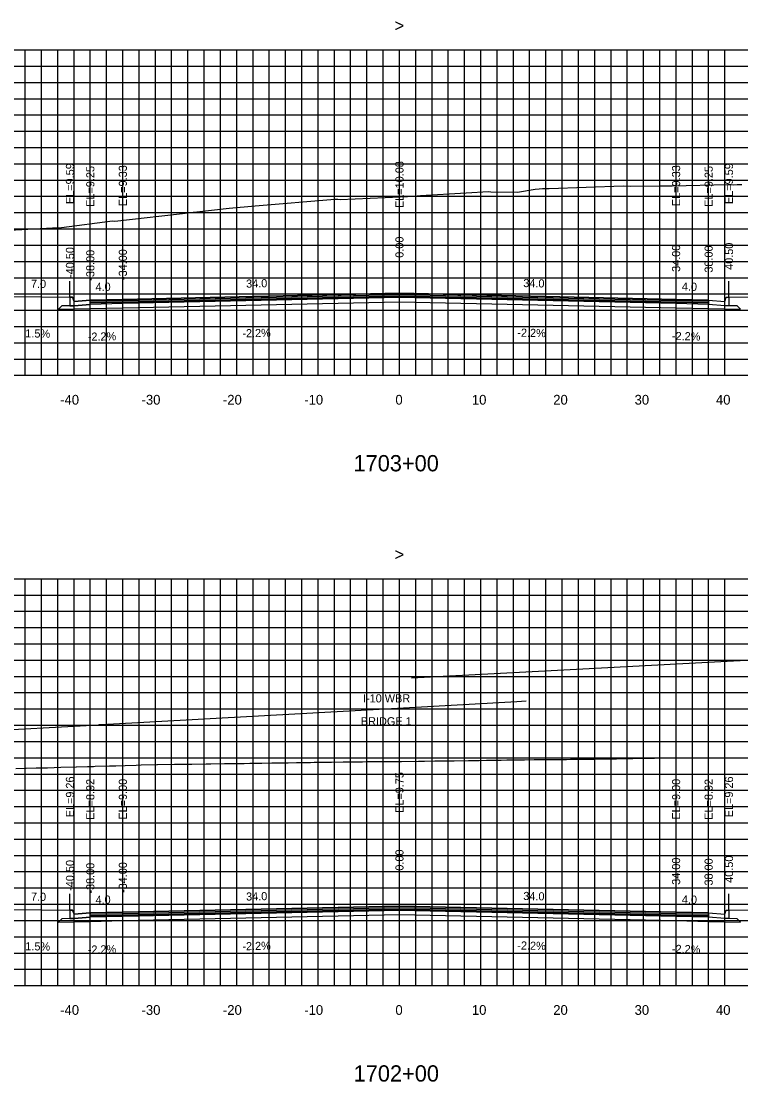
# Model space of a CAD drawing. Extents: x 1797789 to 1803805, y 249066 to 250293.
# Drawn here: x 1802584.5 to 1802673, y 250087.6 to 250218 of the extents above; entities that cross this region are included whole.
import ezdxf

# ---------------------------------------------------------------- set-up
doc = ezdxf.new("R2010")
doc.units = 0
for name, color, linetype in [('1', 7, 'Continuous'), ('10', 7, 'Continuous'), ('3', 7, 'Continuous'), ('4', 7, 'Continuous'), ('60', 7, 'Continuous'), ('BASE', 7, 'Continuous'), ('CL-CNST', 7, 'Continuous'), ('Level 62', 7, 'Continuous'), ('LOWER BINDER', 7, 'Continuous'), ('M-ROADS', 7, 'Continuous'), ('UPPER BINDER', 7, 'Continuous'), ('WEARING', 7, 'Continuous')]:
    doc.layers.add(name, color=color, linetype=linetype)

msp = doc.modelspace()

# ---------------------------------------------------------------- linework, layer by layer
for p, q in [((1802631, 250184.51), (1802631, 250186.51)), ((1802590.5, 250184.02), (1802590.5, 250186.02)), ((1802590.5, 250184.02), (1802590.5, 250186.02)), ((1802593, 250183.68), (1802593, 250185.68)), ((1802597, 250183.77), (1802597, 250185.77)), ((1802665, 250183.77), (1802665, 250185.77)), ((1802669, 250183.68), (1802669, 250185.68)), ((1802671.5, 250184.02), (1802671.5, 250186.02)), ((1802671.5, 250184.02), (1802671.5, 250186.02)), ((1802631, 250109.18), (1802631, 250111.18)), ((1802590.5, 250108.69), (1802590.5, 250110.69)), ((1802590.5, 250108.69), (1802590.5, 250110.69)), ((1802593, 250108.35), (1802593, 250110.35)), ((1802597, 250108.44), (1802597, 250110.44)), ((1802665, 250108.44), (1802665, 250110.44)), ((1802669, 250108.35), (1802669, 250110.35)), ((1802671.5, 250108.69), (1802671.5, 250110.69)), ((1802671.5, 250108.69), (1802671.5, 250110.69))]:
    msp.add_line(p, q)
for points in [[(1802593, 250183.68), (1802591, 250183.52), (1802590.83, 250184.02), (1802590.5, 250184.02), (1802590.5, 250182.99), (1802591, 250182.99), (1802593, 250183.15)], [(1802669, 250183.68), (1802671, 250183.52), (1802671.17, 250184.02), (1802671.5, 250184.02), (1802671.5, 250182.99), (1802671, 250182.99), (1802669, 250183.15)], [(1802593, 250108.35), (1802591, 250108.19), (1802590.83, 250108.69), (1802590.5, 250108.69), (1802590.5, 250107.66), (1802591, 250107.66), (1802593, 250107.82)], [(1802669, 250108.35), (1802671, 250108.19), (1802671.17, 250108.69), (1802671.5, 250108.69), (1802671.5, 250107.66), (1802671, 250107.66), (1802669, 250107.82)]]:
    msp.add_lwpolyline(points, close=True)
at = {"layer": '60'}
for p, q in [((1802481, 250174.43), (1802781, 250174.43)), ((1802591, 250174.37), (1802591, 250174.43)), ((1802601, 250174.37), (1802601, 250174.43)), ((1802611, 250174.37), (1802611, 250174.43)), ((1802621, 250174.37), (1802621, 250174.43)), ((1802631, 250174.37), (1802631, 250174.43)), ((1802641, 250174.37), (1802641, 250174.43)), ((1802651, 250174.37), (1802651, 250174.43)), ((1802661, 250174.37), (1802661, 250174.43)), ((1802671, 250174.37), (1802671, 250174.43)), ((1802481, 250099.43), (1802781, 250099.43)), ((1802591, 250099.37), (1802591, 250099.43)), ((1802601, 250099.37), (1802601, 250099.43)), ((1802611, 250099.37), (1802611, 250099.43)), ((1802621, 250099.37), (1802621, 250099.43)), ((1802631, 250099.37), (1802631, 250099.43)), ((1802641, 250099.37), (1802641, 250099.43)), ((1802651, 250099.37), (1802651, 250099.43)), ((1802661, 250099.37), (1802661, 250099.43)), ((1802671, 250099.37), (1802671, 250099.43))]:
    msp.add_line(p, q, dxfattribs=at)
at = {"layer": 'BASE'}
for points in [[(1802669, 250182.65), (1802672.9, 250182.56), (1802672.5, 250182.97), (1802671.5, 250182.99), (1802671, 250182.99), (1802669, 250183.15), (1802665, 250183.24), (1802631, 250183.98), (1802597, 250183.24), (1802593, 250183.15), (1802591, 250182.99), (1802590.5, 250182.99), (1802589.5, 250182.97), (1802589.1, 250182.56), (1802593, 250182.65), (1802597, 250182.74), (1802631, 250183.48), (1802665, 250182.74)], [(1802669, 250107.32), (1802672.9, 250107.23), (1802672.5, 250107.64), (1802671.5, 250107.66), (1802671, 250107.66), (1802669, 250107.82), (1802665, 250107.91), (1802631, 250108.65), (1802597, 250107.91), (1802593, 250107.82), (1802591, 250107.66), (1802590.5, 250107.66), (1802589.5, 250107.64), (1802589.1, 250107.23), (1802593, 250107.32), (1802597, 250107.41), (1802631, 250108.15), (1802665, 250107.41)]]:
    msp.add_lwpolyline(points, close=True, dxfattribs=at)
at = {"layer": 'CL-CNST'}
for points in [[(1802481, 250187.57), (1802582.5, 250184.16), (1802583.5, 250184.12), (1802590.5, 250184.02), (1802590.5, 250184.02), (1802590.83, 250184.02), (1802591, 250183.52), (1802593, 250183.68), (1802597, 250183.77), (1802631, 250184.51), (1802665, 250183.77), (1802669, 250183.68), (1802671, 250183.52), (1802671.17, 250184.02), (1802671.5, 250184.02), (1802671.5, 250184.02), (1802678.5, 250184.12), (1802679.5, 250184.16), (1802781, 250184.59)], [(1802632.47, 250137.25), (1802644.2, 250137.87), (1802653.52, 250138.36), (1802665.04, 250138.96), (1802679.9, 250139.73), (1802688.39, 250140.16), (1802691.29, 250140.31), (1802692.92, 250140.4), (1802696.16, 250140.56), (1802706.65, 250141.08), (1802715.8, 250141.54), (1802725.76, 250141.98), (1802729.55, 250142.04), (1802733.81, 250142.1), (1802742.28, 250142.22), (1802749.58, 250142.28), (1802750.71, 250142.3), (1802752.52, 250142.31)], [(1802481, 250125.67), (1802485.7, 250125.45), (1802489.05, 250125.3), (1802499.2, 250124.76), (1802500.03, 250124.72), (1802503.77, 250124.83), (1802509.21, 250124.99), (1802512.64, 250125.27), (1802514, 250125.39), (1802517.65, 250125.7), (1802540.82, 250127.67), (1802567.56, 250130.03), (1802570.52, 250130.2), (1802572.85, 250130.32), (1802578.86, 250130.66), (1802593.99, 250131.49), (1802594.15, 250131.5), (1802594.36, 250131.51), (1802632.25, 250133.61), (1802645.42, 250134.34), (1802646.58, 250134.41)], [(1802529.01, 250126.66), (1802582.5, 250108.83), (1802583.5, 250108.79), (1802590.5, 250108.69), (1802590.5, 250108.69), (1802590.83, 250108.69), (1802591, 250108.19), (1802593, 250108.35), (1802597, 250108.44), (1802631, 250109.18), (1802665, 250108.44), (1802669, 250108.35), (1802671, 250108.19), (1802671.17, 250108.69), (1802671.5, 250108.69), (1802671.5, 250108.69), (1802678.5, 250108.79), (1802679.5, 250108.83), (1802781, 250109.41)]]:
    msp.add_lwpolyline(points, dxfattribs=at)
at = {"layer": 'Level 62'}
for p, q in [((1802481, 250214.43), (1802781, 250214.43)), ((1802585, 250174.43), (1802585, 250214.43)), ((1802587, 250174.43), (1802587, 250214.43)), ((1802589, 250174.43), (1802589, 250214.43)), ((1802591, 250174.43), (1802591, 250214.43)), ((1802593, 250174.43), (1802593, 250214.43)), ((1802595, 250174.43), (1802595, 250214.43)), ((1802597, 250174.43), (1802597, 250214.43)), ((1802599, 250174.43), (1802599, 250214.43)), ((1802601, 250174.43), (1802601, 250214.43)), ((1802603, 250174.43), (1802603, 250214.43)), ((1802605, 250174.43), (1802605, 250214.43)), ((1802607, 250174.43), (1802607, 250214.43)), ((1802609, 250174.43), (1802609, 250214.43)), ((1802611, 250174.43), (1802611, 250214.43)), ((1802613, 250174.43), (1802613, 250214.43)), ((1802615, 250174.43), (1802615, 250214.43)), ((1802617, 250174.43), (1802617, 250214.43)), ((1802619, 250174.43), (1802619, 250214.43)), ((1802621, 250174.43), (1802621, 250214.43)), ((1802623, 250174.43), (1802623, 250214.43)), ((1802625, 250174.43), (1802625, 250214.43)), ((1802627, 250174.43), (1802627, 250214.43)), ((1802629, 250174.43), (1802629, 250214.43)), ((1802631, 250174.43), (1802631, 250214.43)), ((1802633, 250174.43), (1802633, 250214.43)), ((1802635, 250174.43), (1802635, 250214.43)), ((1802637, 250174.43), (1802637, 250214.43)), ((1802639, 250174.43), (1802639, 250214.43)), ((1802641, 250174.43), (1802641, 250214.43)), ((1802643, 250174.43), (1802643, 250214.43)), ((1802645, 250174.43), (1802645, 250214.43)), ((1802647, 250174.43), (1802647, 250214.43)), ((1802649, 250174.43), (1802649, 250214.43)), ((1802651, 250174.43), (1802651, 250214.43)), ((1802653, 250174.43), (1802653, 250214.43)), ((1802655, 250174.43), (1802655, 250214.43)), ((1802657, 250174.43), (1802657, 250214.43)), ((1802659, 250174.43), (1802659, 250214.43)), ((1802661, 250174.43), (1802661, 250214.43)), ((1802663, 250174.43), (1802663, 250214.43)), ((1802665, 250174.43), (1802665, 250214.43)), ((1802667, 250174.43), (1802667, 250214.43)), ((1802669, 250174.43), (1802669, 250214.43)), ((1802671, 250174.43), (1802671, 250214.43)), ((1802481, 250212.43), (1802781, 250212.43)), ((1802481, 250210.43), (1802781, 250210.43)), ((1802481, 250208.43), (1802781, 250208.43)), ((1802481, 250206.43), (1802781, 250206.43)), ((1802481, 250204.43), (1802781, 250204.43)), ((1802481, 250202.43), (1802781, 250202.43)), ((1802481, 250200.43), (1802781, 250200.43)), ((1802481, 250198.43), (1802781, 250198.43)), ((1802481, 250196.43), (1802781, 250196.43)), ((1802481, 250194.43), (1802781, 250194.43)), ((1802481, 250192.43), (1802781, 250192.43)), ((1802481, 250190.43), (1802781, 250190.43)), ((1802481, 250188.43), (1802781, 250188.43)), ((1802481, 250186.43), (1802781, 250186.43)), ((1802481, 250184.43), (1802781, 250184.43)), ((1802481, 250182.43), (1802781, 250182.43)), ((1802481, 250180.43), (1802781, 250180.43)), ((1802481, 250178.43), (1802781, 250178.43)), ((1802481, 250176.43), (1802781, 250176.43)), ((1802481, 250174.43), (1802781, 250174.43)), ((1802481, 250149.43), (1802781, 250149.43)), ((1802585, 250099.43), (1802585, 250149.43)), ((1802587, 250099.43), (1802587, 250149.43)), ((1802589, 250099.43), (1802589, 250149.43)), ((1802591, 250099.43), (1802591, 250149.43)), ((1802593, 250099.43), (1802593, 250149.43)), ((1802595, 250099.43), (1802595, 250149.43)), ((1802597, 250099.43), (1802597, 250149.43)), ((1802599, 250099.43), (1802599, 250149.43)), ((1802601, 250099.43), (1802601, 250149.43)), ((1802603, 250099.43), (1802603, 250149.43)), ((1802605, 250099.43), (1802605, 250149.43)), ((1802607, 250099.43), (1802607, 250149.43)), ((1802609, 250099.43), (1802609, 250149.43)), ((1802611, 250099.43), (1802611, 250149.43)), ((1802613, 250099.43), (1802613, 250149.43)), ((1802615, 250099.43), (1802615, 250149.43)), ((1802617, 250099.43), (1802617, 250149.43)), ((1802619, 250099.43), (1802619, 250149.43)), ((1802621, 250099.43), (1802621, 250149.43)), ((1802623, 250099.43), (1802623, 250149.43)), ((1802625, 250099.43), (1802625, 250149.43)), ((1802627, 250099.43), (1802627, 250149.43)), ((1802629, 250099.43), (1802629, 250149.43)), ((1802631, 250099.43), (1802631, 250149.43)), ((1802633, 250099.43), (1802633, 250149.43)), ((1802635, 250099.43), (1802635, 250149.43)), ((1802637, 250099.43), (1802637, 250149.43)), ((1802639, 250099.43), (1802639, 250149.43)), ((1802641, 250099.43), (1802641, 250149.43)), ((1802643, 250099.43), (1802643, 250149.43)), ((1802645, 250099.43), (1802645, 250149.43)), ((1802647, 250099.43), (1802647, 250149.43)), ((1802649, 250099.43), (1802649, 250149.43)), ((1802651, 250099.43), (1802651, 250149.43)), ((1802653, 250099.43), (1802653, 250149.43)), ((1802655, 250099.43), (1802655, 250149.43)), ((1802657, 250099.43), (1802657, 250149.43)), ((1802659, 250099.43), (1802659, 250149.43)), ((1802661, 250099.43), (1802661, 250149.43)), ((1802663, 250099.43), (1802663, 250149.43)), ((1802665, 250099.43), (1802665, 250149.43)), ((1802667, 250099.43), (1802667, 250149.43)), ((1802669, 250099.43), (1802669, 250149.43)), ((1802671, 250099.43), (1802671, 250149.43)), ((1802481, 250147.43), (1802781, 250147.43)), ((1802481, 250145.43), (1802781, 250145.43)), ((1802481, 250143.43), (1802781, 250143.43)), ((1802481, 250141.43), (1802781, 250141.43)), ((1802481, 250139.43), (1802781, 250139.43)), ((1802481, 250137.43), (1802781, 250137.43)), ((1802481, 250135.43), (1802781, 250135.43)), ((1802481, 250133.43), (1802781, 250133.43)), ((1802481, 250131.43), (1802781, 250131.43)), ((1802481, 250129.43), (1802781, 250129.43)), ((1802481, 250127.43), (1802781, 250127.43)), ((1802481, 250125.43), (1802781, 250125.43)), ((1802481, 250123.43), (1802781, 250123.43)), ((1802481, 250121.43), (1802781, 250121.43)), ((1802481, 250119.43), (1802781, 250119.43)), ((1802481, 250117.43), (1802781, 250117.43)), ((1802481, 250115.43), (1802781, 250115.43)), ((1802481, 250113.43), (1802781, 250113.43)), ((1802481, 250111.43), (1802781, 250111.43)), ((1802481, 250109.43), (1802781, 250109.43)), ((1802481, 250107.43), (1802781, 250107.43)), ((1802481, 250105.43), (1802781, 250105.43)), ((1802481, 250103.43), (1802781, 250103.43)), ((1802481, 250101.43), (1802781, 250101.43)), ((1802481, 250099.43), (1802781, 250099.43))]:
    msp.add_line(p, q, dxfattribs=at)
at = {"layer": 'LOWER BINDER'}
for points in [[(1802593, 250183.15), (1802593, 250183.34), (1802597, 250183.43), (1802631, 250184.17), (1802665, 250183.43), (1802669, 250183.34), (1802669, 250183.15), (1802665, 250183.24), (1802631, 250183.98), (1802597, 250183.24)], [(1802593, 250107.82), (1802593, 250108.01), (1802597, 250108.1), (1802631, 250108.84), (1802665, 250108.1), (1802669, 250108.01), (1802669, 250107.82), (1802665, 250107.91), (1802631, 250108.65), (1802597, 250107.91)]]:
    msp.add_lwpolyline(points, close=True, dxfattribs=at)
at = {"layer": 'M-ROADS'}
for points in [[(1802573.92, 250191.76), (1802588.37, 250192.57), (1802588.4, 250192.56), (1802588.89, 250192.55), (1802589.05, 250192.55), (1802589.27, 250192.55), (1802589.48, 250192.58), (1802595.71, 250193.42), (1802596, 250193.39), (1802605.4, 250194.44), (1802605.64, 250194.47), (1802606.09, 250194.52), (1802610.07, 250194.98), (1802613.26, 250195.27), (1802623.07, 250196.07), (1802623.29, 250196.1), (1802623.42, 250196.08), (1802623.7, 250196.03), (1802632.93, 250196.46), (1802633.19, 250196.48), (1802633.58, 250196.52), (1802639.2, 250196.87), (1802641.96, 250197.02), (1802642.25, 250197), (1802645.49, 250196.95), (1802647.69, 250197.31), (1802648.17, 250197.36), (1802648.6, 250197.39), (1802648.62, 250197.39), (1802649.42, 250197.38), (1802658.51, 250197.72), (1802659.41, 250197.69), (1802663.01, 250197.7), (1802663.28, 250197.71), (1802664.53, 250197.73), (1802671.36, 250197.87), (1802671.74, 250197.88), (1802671.76, 250197.88), (1802672.05, 250197.86), (1802672.5, 250197.87), (1802673.1, 250197.89)], [(1802583.86, 250126.11), (1802584.98, 250126.14), (1802585.1, 250126.14), (1802586.33, 250126.17), (1802587.74, 250126.21), (1802589.37, 250126.26), (1802591.28, 250126.31), (1802591.31, 250126.31), (1802592.67, 250126.35), (1802593.38, 250126.37), (1802593.59, 250126.38), (1802595.34, 250126.43), (1802596.12, 250126.45), (1802597.29, 250126.49), (1802598.65, 250126.52), (1802599.25, 250126.54), (1802601.18, 250126.6), (1802601.21, 250126.6), (1802601.28, 250126.6), (1802603.34, 250126.63), (1802603.34, 250126.63), (1802605.24, 250126.65), (1802605.49, 250126.66), (1802607.26, 250126.68), (1802607.64, 250126.68), (1802607.82, 250126.69), (1802609.49, 250126.71), (1802609.78, 250126.71), (1802611.29, 250126.73), (1802611.93, 250126.74), (1802612.62, 250126.75), (1802614.03, 250126.77), (1802614.07, 250126.77), (1802615.32, 250126.79), (1802616.22, 250126.8), (1802617.33, 250126.82), (1802618.36, 250126.84), (1802618.88, 250126.84), (1802619.4, 250126.85), (1802620.06, 250126.86), (1802620.51, 250126.87), (1802621.84, 250126.89), (1802622.66, 250126.9), (1802624.07, 250126.93), (1802624.73, 250126.94), (1802624.8, 250126.94), (1802626.44, 250126.94), (1802626.95, 250126.95), (1802628.74, 250126.95), (1802629.09, 250126.95), (1802629.94, 250126.96), (1802630.21, 250126.96), (1802631.24, 250126.97), (1802633.34, 250127), (1802633.39, 250127.01), (1802634.06, 250127.02), (1802635.36, 250127.03), (1802635.44, 250127.03), (1802635.53, 250127.04), (1802635.54, 250127.04), (1802637.46, 250127.06), (1802637.71, 250127.07), (1802639.48, 250127.09), (1802639.87, 250127.1), (1802640.64, 250127.11), (1802640.8, 250127.11), (1802641.68, 250127.13), (1802642.03, 250127.13), (1802643.52, 250127.15), (1802644.2, 250127.16), (1802645.48, 250127.17), (1802646.16, 250127.18), (1802646.22, 250127.18), (1802646.36, 250127.19), (1802647.56, 250127.2), (1802648.52, 250127.21), (1802649.58, 250127.22), (1802650.69, 250127.23), (1802651.12, 250127.23), (1802651.53, 250127.23), (1802652.01, 250127.24), (1802652.85, 250127.25), (1802653.62, 250127.26), (1802655.01, 250127.27), (1802655.62, 250127.28), (1802656.89, 250127.29), (1802656.92, 250127.29), (1802657.18, 250127.3), (1802657.66, 250127.3), (1802659.34, 250127.33), (1802659.68, 250127.34), (1802661.5, 250127.37), (1802661.6, 250127.37), (1802662.26, 250127.38), (1802662.34, 250127.38), (1802663.67, 250127.4), (1802663.72, 250127.4), (1802664.53, 250127.41), (1802665.75, 250127.41), (1802665.84, 250127.41), (1802667.7, 250127.41), (1802667.94, 250127.41), (1802668.02, 250127.41), (1802669.81, 250127.41), (1802670.19, 250127.41), (1802671.84, 250127.41), (1802672.37, 250127.41), (1802673.09, 250127.41)]]:
    msp.add_lwpolyline(points, dxfattribs=at)
at = {"layer": 'UPPER BINDER'}
for points in [[(1802631, 250184.17), (1802597, 250183.43), (1802593, 250183.34), (1802593, 250183.53), (1802597, 250183.62), (1802631, 250184.36), (1802665, 250183.62), (1802669, 250183.53), (1802669, 250183.15), (1802669, 250183.34), (1802665, 250183.43)], [(1802631, 250108.84), (1802597, 250108.1), (1802593, 250108.01), (1802593, 250108.2), (1802597, 250108.29), (1802631, 250109.03), (1802665, 250108.29), (1802669, 250108.2), (1802669, 250107.82), (1802669, 250108.01), (1802665, 250108.1)]]:
    msp.add_lwpolyline(points, close=True, dxfattribs=at)
at = {"layer": 'WEARING'}
for points in [[(1802669, 250183.53), (1802669, 250183.68), (1802665, 250183.77), (1802631, 250184.51), (1802597, 250183.77), (1802593, 250183.68), (1802593, 250183.53), (1802597, 250183.62), (1802631, 250184.36), (1802665, 250183.62)], [(1802669, 250108.2), (1802669, 250108.35), (1802665, 250108.44), (1802631, 250109.18), (1802597, 250108.44), (1802593, 250108.35), (1802593, 250108.2), (1802597, 250108.29), (1802631, 250109.03), (1802665, 250108.29)]]:
    msp.add_lwpolyline(points, close=True, dxfattribs=at)

# ---------------------------------------------------------------- texts
at = {"layer": '1'}
for s, p in [('1703+00', (1802625.35, 250162.63)), ('1702+00', (1802625.37, 250087.63))]:
    msp.add_text(s, height=2, dxfattribs=at).set_placement(p)
at = {"layer": '10'}
for s, p in [('-40', (1802589.3, 250170.83)), ('-30', (1802599.3, 250170.83)), ('-20', (1802609.3, 250170.83)), ('-10', (1802619.3, 250170.83)), ('0', (1802630.5, 250170.83)), ('10', (1802639.9, 250170.83)), ('20', (1802649.9, 250170.83)), ('30', (1802659.9, 250170.83)), ('40', (1802669.9, 250170.83)), ('-40', (1802589.3, 250095.83)), ('-30', (1802599.3, 250095.83)), ('-20', (1802609.3, 250095.83)), ('-10', (1802619.3, 250095.83)), ('0', (1802630.5, 250095.83)), ('10', (1802639.9, 250095.83)), ('20', (1802649.9, 250095.83)), ('30', (1802659.9, 250095.83)), ('40', (1802669.9, 250095.83))]:
    msp.add_text(s, height=1.2, dxfattribs=at).set_placement(p)
at = {"layer": '3'}
for s, p in [('EL=10.08', (1802631.5, 250194.99)), ('EL=9.59', (1802591, 250195.48)), ('EL=9.59', (1802591, 250195.48)), ('EL=9.25', (1802593.5, 250195.14)), ('EL=9.33', (1802597.5, 250195.23)), ('EL=9.33', (1802665.5, 250195.23)), ('EL=9.25', (1802669.5, 250195.14)), ('EL=9.59', (1802672, 250195.48)), ('EL=9.59', (1802672, 250195.48)), ('0.00', (1802631.5, 250188.88)), ('34.00', (1802665.5, 250187.14)), ('38.00', (1802669.5, 250187.05)), ('40.50', (1802672, 250187.39)), ('40.50', (1802672, 250187.39)), ('-40.50', (1802591, 250186.4)), ('-40.50', (1802591, 250186.4)), ('-38.00', (1802593.5, 250186.06)), ('-34.00', (1802597.5, 250186.14)), ('EL=9.26', (1802591, 250120.11)), ('EL=9.26', (1802591, 250120.11)), ('EL=9.75', (1802631.5, 250120.65)), ('EL=9.26', (1802672, 250120.11)), ('EL=9.26', (1802672, 250120.11)), ('EL=8.92', (1802593.5, 250119.81)), ('EL=9.00', (1802597.5, 250119.82)), ('EL=9.00', (1802665.5, 250119.82)), ('EL=8.92', (1802669.5, 250119.81)), ('0.00', (1802631.5, 250113.55)), ('-40.50', (1802591, 250111.07)), ('-40.50', (1802591, 250111.07)), ('34.00', (1802665.5, 250111.81)), ('38.00', (1802669.5, 250111.72)), ('40.50', (1802672, 250112.06)), ('40.50', (1802672, 250112.06)), ('-38.00', (1802593.5, 250110.73)), ('-34.00', (1802597.5, 250110.81))]:
    msp.add_text(s, height=1, rotation=90, dxfattribs=at).set_placement(p)
for s, p in [('I-10 WBR ', (1802626.52, 250134.23)), ('BRIDGE 1', (1802626.26, 250131.41))]:
    msp.add_text(s, height=1, dxfattribs=at).set_placement(p)
at = {"layer": '4'}
for s, rotation, p in [('7.0', 359.1406, (1802585.7, 250185.19)), ('4.0', 1.2603, (1802593.65, 250184.79)), ('34.0', 1.2603, (1802612.16, 250185.2)), ('34.0', 358.7397, (1802646.21, 250185.28)), ('4.0', 358.7397, (1802665.7, 250184.85)), ('1.5%', 359.1406, (1802585.01, 250179.1)), ('-2.2%', 1.2603, (1802611.7, 250179.09)), ('-2.2%', 358.7397, (1802645.48, 250179.19)), ('-2.2%', 1.2603, (1802592.7, 250178.67)), ('-2.2%', 358.7397, (1802664.48, 250178.78)), ('7.0', 359.1406, (1802585.7, 250109.86)), ('34.0', 1.2603, (1802612.16, 250109.87)), ('34.0', 358.7397, (1802646.21, 250109.95)), ('4.0', 1.2603, (1802593.65, 250109.46)), ('4.0', 358.7397, (1802665.7, 250109.52)), ('1.5%', 359.1406, (1802585.01, 250103.77)), ('-2.2%', 1.2603, (1802592.7, 250103.34)), ('-2.2%', 1.2603, (1802611.7, 250103.76)), ('-2.2%', 358.7397, (1802645.48, 250103.87)), ('-2.2%', 358.7397, (1802664.48, 250103.45))]:
    msp.add_text(s, height=1, rotation=rotation, dxfattribs=at).set_placement(p)
at = {"layer": '60'}
for p in [(1802630.39, 250216.68), (1802630.39, 250151.68)]:
    msp.add_text('>', height=1.5, dxfattribs=at).set_placement(p)

doc.saveas('drawing.dxf')
